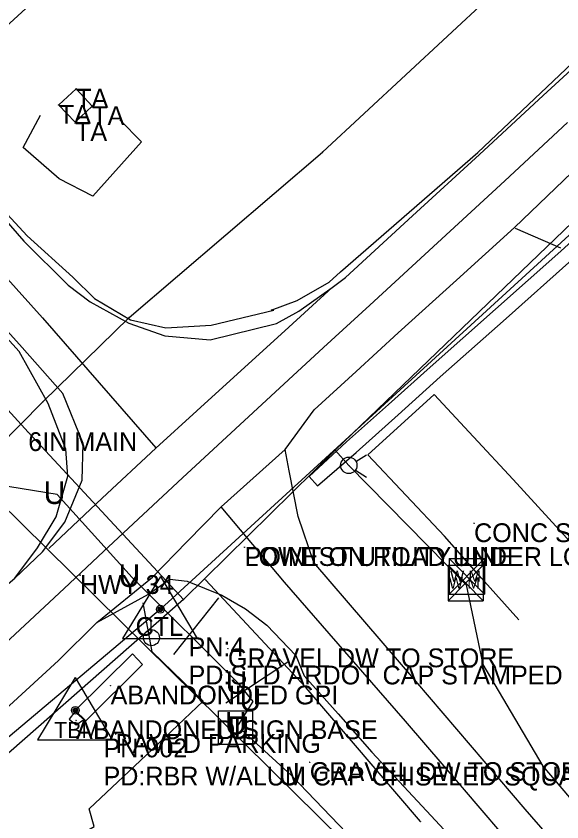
# Model space of a CAD drawing. Extents: x 1660112 to 1662239, y 668919 to 671377.
# Drawn here: x 1661566.2 to 1661711.4, y 669800.5 to 670014.9 of the extents above; entities that cross this region are included whole.
import ezdxf

# ---------------------------------------------------------------- set-up
doc = ezdxf.new("R2010")
doc.units = 0
for name, color, linetype in [('Default', 7, 'Continuous'), ('S_BASELINE', 7, 'Continuous'), ('S_BUILDING', 7, 'Continuous'), ('S_BUILDING_ANNOT', 7, 'Continuous'), ('S_DRIVEWAY', 7, 'Continuous'), ('S_EDGE_CONCRETE', 7, 'Continuous'), ('S_EDGE_PAVEMENT', 7, 'Continuous'), ('S_ELECTRIC_UTILITIES_ANNOT', 7, 'Continuous'), ('S_FIBER_OPTIC_CABLE', 7, 'Continuous'), ('S_MSC_PT_SYM', 7, 'Continuous'), ('S_PAVEMENT_CROWN', 7, 'Continuous'), ('S_PRIMARY_CTL', 7, 'Continuous'), ('S_PRIMARY_CTL_ANNOT', 7, 'Continuous'), ('S_RAILROAD', 7, 'Continuous'), ('S_SANITARY_SEWER', 7, 'Continuous'), ('S_SHOULDER', 7, 'Continuous'), ('S_SIDEWALK', 7, 'Continuous'), ('S_STR_PT_SYM', 7, 'Continuous'), ('S_SURVEY_TEXT_ANNOT', 7, 'Continuous'), ('S_TELEPHONE_UTILITIES', 7, 'Continuous'), ('S_UNDERGROUND_CABLE', 7, 'Continuous'), ('S_UTILITY_POLE', 7, 'Continuous'), ('S_UTL_PT_SYM', 7, 'Continuous'), ('S_WATER_UTILITIES', 7, 'Continuous'), ('S_WATER_UTILITIES_ANNOT', 7, 'Continuous')]:
    doc.layers.add(name, color=color, linetype=linetype)

msp = doc.modelspace()

# ---------------------------------------------------------------- linework, layer by layer
at = {"layer": 'S_BASELINE'}
for p, q in [((1662115.18, 670324.54), (1661604.59, 669857.12)), ((1661604.59, 669857.12), (1660827.54, 669202.71))]:
    msp.add_line(p, q, dxfattribs=at)
at = {"layer": 'S_BUILDING'}
for p, q in [((1661582.19, 669995.6), (1661577.57, 669991.32)), ((1661586.47, 669990.97), (1661582.19, 669995.6)), ((1661577.5, 669991.3), (1661581.89, 669986.74)), ((1661581.89, 669986.74), (1661586.47, 669990.97))]:
    msp.add_line(p, q, dxfattribs=at)
at = {"layer": 'S_DRIVEWAY'}
for points in [[(1661699.03, 669958.54), (1661711.11, 669953.25)], [(1661620.11, 669860.18), (1661608.05, 669845.12)], [(1661638.76, 669843.19), (1661621.98, 669832.17)]]:
    msp.add_lwpolyline(points, dxfattribs=at)
at = {"layer": 'S_EDGE_CONCRETE'}
msp.add_lwpolyline([(1661699.96, 669854.31), (1661690.09, 669865.42), (1661680.21, 669876.53), (1661670, 669887.38), (1661659.78, 669898.24), (1661677.47, 669914.28), (1661687.96, 669902.95), (1661698.44, 669891.62), (1661708.01, 669881.23), (1661717.57, 669870.84)], dxfattribs=at)
for points in [[(1661597.15, 669845.29), (1661581.95, 669830.2), (1661584.79, 669827.42), (1661599.88, 669842.38)], [(1661581.85, 669829.83), (1661580.32, 669827.84), (1661582.15, 669826.33), (1661584.2, 669827.74)]]:
    msp.add_lwpolyline(points, close=True, dxfattribs=at)
at = {"layer": 'S_EDGE_PAVEMENT'}
for points in [[(1661574.88, 669873.32), (1661589.13, 669886.67), (1661603.39, 669900.01), (1661614.27, 669909.9), (1661625.16, 669919.78), (1661637.72, 669931.24), (1661650.28, 669942.7), (1661653.82, 669945.42), (1661671.65, 669961.77), (1661689.49, 669978.13), (1661706.49, 669993.78), (1661723.49, 670009.42), (1661733.12, 670018.24), (1661742.75, 670027.06), (1661756.74, 670039.98), (1661772.34, 670054.33), (1661787.94, 670068.68), (1661803.44, 670083.1), (1661818.95, 670097.53)], [(1661527.23, 669797.8), (1661542.56, 669811.61), (1661560.01, 669827.54), (1661577.47, 669843.46), (1661587.7, 669853.61), (1661602.47, 669865.64), (1661611.61, 669875.02), (1661620.74, 669884.39), (1661637.78, 669899.63), (1661645.56, 669910.14), (1661656.74, 669920.41), (1661667.92, 669930.69), (1661683.38, 669944.69), (1661698.84, 669958.7), (1661714.13, 669973.35), (1661725.28, 669983.31), (1661736.44, 669993.26), (1661746.57, 670002.69), (1661756.7, 670012.13), (1661762.09, 670016.26), (1661771.92, 670025.7), (1661786.96, 670039.58), (1661802.01, 670053.47)], [(1661593.85, 669987.34), (1661599.58, 669981.47), (1661586.66, 669967), (1661577.69, 669971.61), (1661568.05, 669980.02), (1661572.66, 669988.57)], [(1661539.87, 669986.88), (1661549.09, 669976.87), (1661558.69, 669965.95), (1661568.29, 669955.03), (1661580.08, 669943.31), (1661585.93, 669938.89), (1661596.24, 669933.25), (1661605.77, 669929.84), (1661617.85, 669928.83), (1661635.53, 669933.18), (1661641.44, 669936.4), (1661650.28, 669942.7)], [(1661432.01, 669741.93), (1661449.2, 669757.82), (1661461.17, 669768.88), (1661473.15, 669779.94), (1661485.12, 669791), (1661497.09, 669802.06), (1661512.08, 669815.85), (1661527.07, 669829.65), (1661544.05, 669845.51), (1661561.04, 669861.38), (1661565.83, 669865.41), (1661573.24, 669872.37), (1661579.19, 669880.3), (1661583.76, 669891.47), (1661584.04, 669901.2), (1661578.64, 669914.49), (1661567.83, 669926.75), (1661553.64, 669942.48), (1661544.41, 669952.61), (1661535.19, 669962.75), (1661525.02, 669973.56)], [(1661814.09, 669678.75), (1661801.76, 669692.17), (1661789.43, 669705.59), (1661777.09, 669719), (1661764.76, 669732.42), (1661756.13, 669742.08), (1661747.5, 669751.75), (1661738.87, 669761.41), (1661730.24, 669771.08), (1661715.94, 669787.51), (1661701.63, 669803.94), (1661687.11, 669820.98), (1661672.59, 669838.02), (1661659.03, 669853.81), (1661645.46, 669869.6), (1661641.26, 669881.81), (1661638.86, 669893.94), (1661637.77, 669899.62)], [(1661587.69, 669853.6), (1661601.46, 669861.14), (1661607.16, 669865.14), (1661611.7, 669864.55), (1661620.99, 669860.83), (1661627.24, 669857.2), (1661632.97, 669852.86), (1661640.64, 669844.85), (1661642.88, 669839.37), (1661651.88, 669829.25), (1661660.88, 669819.13), (1661676.63, 669802.18), (1661692.38, 669785.23), (1661706.18, 669769.2), (1661719.98, 669753.17), (1661729.11, 669743.19), (1661738.25, 669733.2), (1661747.38, 669723.22), (1661756.51, 669713.23), (1661766.96, 669701.85), (1661777.42, 669690.46), (1661787.87, 669679.07), (1661798.32, 669667.68)], [(1661516.06, 669787.26), (1661526.46, 669785.99), (1661541.4, 669768), (1661544.7, 669763.68), (1661549.49, 669767.62), (1661547.73, 669791.69), (1661563.07, 669792.95), (1661578.42, 669794.22), (1661586.99, 669799.3), (1661585.63, 669803.97), (1661600.8, 669818.33), (1661615.97, 669832.69), (1661602.41, 669845.81), (1661600.05, 669858.83)]]:
    msp.add_lwpolyline(points, dxfattribs=at)
at = {"layer": 'S_FIBER_OPTIC_CABLE'}
for p, q in [((1661647.72, 669978.74), (1661720.75, 670046.56)), ((1661596.3, 669934.77), (1661647.72, 669978.74)), ((1661573.33, 669912.35), (1661596.3, 669934.77)), ((1661539.32, 669878.16), (1661573.33, 669912.35))]:
    msp.add_line(p, q, dxfattribs=at)
at = {"layer": 'S_MSC_PT_SYM'}
for points in [[(1661688.07, 669879.98), (1661688.07, 669880.03), (1661688.07, 669879.98), (1661688.02, 669879.98), (1661688.07, 669879.98), (1661688.07, 669879.93), (1661688.07, 669879.98), (1661688.12, 669879.98)], [(1661627.02, 669873.64), (1661627.02, 669873.69), (1661627.02, 669873.64), (1661626.97, 669873.64), (1661627.02, 669873.64), (1661627.02, 669873.59), (1661627.02, 669873.64), (1661627.07, 669873.64)], [(1661583.22, 669866.19), (1661583.22, 669866.24), (1661583.22, 669866.19), (1661583.17, 669866.19), (1661583.22, 669866.19), (1661583.22, 669866.14), (1661583.22, 669866.19), (1661583.27, 669866.19)], [(1661622.59, 669846.68), (1661622.59, 669846.73), (1661622.59, 669846.68), (1661622.54, 669846.68), (1661622.59, 669846.68), (1661622.59, 669846.63), (1661622.59, 669846.68), (1661622.64, 669846.68)], [(1661591.37, 669836.8), (1661591.37, 669836.85), (1661591.37, 669836.8), (1661591.32, 669836.8), (1661591.37, 669836.8), (1661591.37, 669836.75), (1661591.37, 669836.8), (1661591.42, 669836.8)], [(1661582.16, 669827.55), (1661582.16, 669827.6), (1661582.16, 669827.55), (1661582.11, 669827.55), (1661582.16, 669827.55), (1661582.16, 669827.5), (1661582.16, 669827.55), (1661582.21, 669827.55)], [(1661592.72, 669823.9), (1661592.72, 669823.95), (1661592.72, 669823.9), (1661592.67, 669823.9), (1661592.72, 669823.9), (1661592.72, 669823.85), (1661592.72, 669823.9), (1661592.77, 669823.9)], [(1661644.36, 669816.42), (1661644.36, 669816.47), (1661644.36, 669816.42), (1661644.31, 669816.42), (1661644.36, 669816.42), (1661644.36, 669816.37), (1661644.36, 669816.42), (1661644.41, 669816.42)]]:
    msp.add_lwpolyline(points, dxfattribs=at)
at = {"layer": 'S_PAVEMENT_CROWN'}
for points in [[(1661503.87, 669793.54), (1661518.86, 669807.19), (1661533.86, 669820.84), (1661551.21, 669836.85), (1661568.55, 669852.86), (1661579.03, 669862.68), (1661589.51, 669872.49), (1661600, 669882.3), (1661610.48, 669892.12), (1661619.87, 669900.79), (1661629.26, 669909.46), (1661638.66, 669918.13), (1661648.05, 669926.8), (1661660.37, 669938.02), (1661678.3, 669954.58), (1661696.23, 669971.14), (1661712.97, 669986.61)], [(1661532.25, 669980.05), (1661542.23, 669969.08), (1661553.09, 669957.19), (1661563.16, 669945.92), (1661573.22, 669934.64), (1661588.29, 669917.36), (1661603.37, 669900.08)], [(1661620.71, 669884.35), (1661629.13, 669874.34), (1661637.54, 669864.33), (1661653.63, 669845.85), (1661669.73, 669827.36), (1661684.9, 669809.66), (1661700.07, 669791.96), (1661714.09, 669775.77), (1661728.11, 669759.57), (1661736.98, 669749.7), (1661745.86, 669739.83), (1661754.73, 669729.96), (1661763.61, 669720.09), (1661774.08, 669708.76), (1661784.55, 669697.43), (1661795.03, 669686.1), (1661805.5, 669674.77)]]:
    msp.add_lwpolyline(points, dxfattribs=at)
at = {"layer": 'S_PRIMARY_CTL'}
for p, q in [((1661604.59, 669865.82), (1661594.55, 669849.3)), ((1661604.59, 669865.82), (1661614.41, 669849.3)), ((1661594.55, 669849.3), (1661614.41, 669849.3)), ((1661581.97, 669838.92), (1661571.93, 669822.4)), ((1661581.97, 669838.92), (1661591.79, 669822.4)), ((1661571.93, 669822.4), (1661591.79, 669822.4))]:
    msp.add_line(p, q, dxfattribs=at)
for centre, radius in [((1661604.59, 669857.12), 1.04), ((1661604.59, 669857.12), 0.609), ((1661604.59, 669857.12), 0.344), ((1661581.97, 669830.22), 1.04), ((1661581.97, 669830.22), 0.609), ((1661581.97, 669830.22), 0.344)]:
    msp.add_circle(centre, radius, dxfattribs=at)
at = {"layer": 'S_RAILROAD'}
msp.add_line((1661541.88, 669992.49), (1661596.12, 670041.9), dxfattribs=at)
at = {"layer": 'S_SANITARY_SEWER'}
msp.add_line((1661704.02, 669745.54), (1661292.91, 670150.69), dxfattribs=at)
at = {"layer": 'S_SHOULDER'}
for points in [[(1661544.18, 669990.78), (1661545.38, 669989.16), (1661549.73, 669977.29), (1661559.45, 669966.88), (1661569.17, 669956.48), (1661581.29, 669945.51), (1661587.1, 669939.82), (1661596.61, 669934.16), (1661606.09, 669931.97), (1661618.1, 669932.69), (1661634.83, 669936.71), (1661634.11, 669936.74), (1661641.01, 669939.29), (1661649.51, 669944.11), (1661652.54, 669946.88), (1661670.8, 669962.78), (1661689.06, 669978.67), (1661705.8, 669994.5), (1661722.55, 670010.32)], [(1661565.9, 669865.41), (1661571.88, 669873.46), (1661576.91, 669881.7), (1661580, 669892.53), (1661579.44, 669899.68), (1661574.75, 669911.86), (1661567.03, 669925.66), (1661552.68, 669941.47), (1661543.51, 669951.68), (1661534.34, 669961.89), (1661525.37, 669969.85), (1661523.19, 669968.6), (1661521.62, 669970.1)]]:
    msp.add_lwpolyline(points, dxfattribs=at)
at = {"layer": 'S_SIDEWALK'}
for points in [[(1661646.43, 669889.94), (1661644.23, 669892.47), (1661654.17, 669901.69), (1661665.3, 669911.6), (1661676.42, 669921.52), (1661693.78, 669936.97), (1661711.13, 669952.42), (1661719.33, 669959.85), (1661733.17, 669972.43), (1661747.01, 669985), (1661757.67, 669994.65), (1661768.33, 670004.3), (1661781.51, 670016.3), (1661797.89, 670031.01), (1661814.27, 670045.72), (1661827.95, 670058.03), (1661841.63, 670070.34)], [(1661646.44, 669889.96), (1661656.73, 669898.86), (1661667.89, 669908.89), (1661679.06, 669918.92), (1661696.59, 669934.52), (1661714.11, 669950.11), (1661722.27, 669957.66), (1661735.99, 669969.95), (1661749.7, 669982.24), (1661760.22, 669991.84), (1661770.74, 670001.44), (1661784.06, 670013.42), (1661800.45, 670028.21), (1661816.83, 670043.01), (1661830.55, 670055.24), (1661844.26, 670067.47)]]:
    msp.add_lwpolyline(points, dxfattribs=at)
at = {"layer": 'S_STR_PT_SYM'}
for points in [[(1661582.19, 669995.6), (1661582.19, 669995.65), (1661582.19, 669995.6), (1661582.14, 669995.6), (1661582.19, 669995.6), (1661582.19, 669995.55), (1661582.19, 669995.6), (1661582.24, 669995.6)], [(1661577.5, 669991.3), (1661577.5, 669991.35), (1661577.5, 669991.3), (1661577.45, 669991.3), (1661577.5, 669991.3), (1661577.5, 669991.25), (1661577.5, 669991.3), (1661577.55, 669991.3)], [(1661577.57, 669991.32), (1661577.57, 669991.37), (1661577.57, 669991.32), (1661577.52, 669991.32), (1661577.57, 669991.32), (1661577.57, 669991.27), (1661577.57, 669991.32), (1661577.62, 669991.32)], [(1661586.47, 669990.97), (1661586.47, 669991.02), (1661586.47, 669990.97), (1661586.42, 669990.97), (1661586.47, 669990.97), (1661586.47, 669990.92), (1661586.47, 669990.97), (1661586.52, 669990.97)], [(1661581.89, 669986.74), (1661581.89, 669986.79), (1661581.89, 669986.74), (1661581.84, 669986.74), (1661581.89, 669986.74), (1661581.89, 669986.69), (1661581.89, 669986.74), (1661581.94, 669986.74)]]:
    msp.add_lwpolyline(points, dxfattribs=at)
at = {"layer": 'S_TELEPHONE_UTILITIES'}
msp.add_lwpolyline([(1661620.09, 669821.1), (1661620.09, 669830.1), (1661629.09, 669830.1), (1661629.09, 669821.1)], close=True, dxfattribs=at)
at = {"layer": 'S_UNDERGROUND_CABLE'}
for p, q in [((1661577.17, 669887.67), (1661559.59, 669890.51)), ((1661597.09, 669865.59), (1661577.17, 669887.67)), ((1661625.58, 669837.15), (1661597.09, 669865.59)), ((1661629.29, 669832.59), (1661625.58, 669837.15)), ((1661625.43, 669826.33), (1661629.29, 669832.59)), ((1661639.6, 669812.78), (1661626.1, 669825.11)), ((1661660.31, 669791.28), (1661639.6, 669812.78))]:
    msp.add_line(p, q, dxfattribs=at)
at = {"layer": 'S_UTILITY_POLE'}
msp.add_line((1661602.11, 669851.69), (1661602.11, 669853.8), dxfattribs=at)
msp.add_circle((1661602.23, 669849.55), 2.13, dxfattribs=at)
at = {"layer": 'S_UTL_PT_SYM'}
for points in [[(1661647.72, 669978.74), (1661647.72, 669978.79), (1661647.72, 669978.74), (1661647.67, 669978.74), (1661647.72, 669978.74), (1661647.72, 669978.69), (1661647.72, 669978.74), (1661647.77, 669978.74)], [(1661596.3, 669934.77), (1661596.3, 669934.82), (1661596.3, 669934.77), (1661596.25, 669934.77), (1661596.3, 669934.77), (1661596.3, 669934.72), (1661596.3, 669934.77), (1661596.35, 669934.77)], [(1661573.33, 669912.35), (1661573.33, 669912.4), (1661573.33, 669912.35), (1661573.28, 669912.35), (1661573.33, 669912.35), (1661573.33, 669912.3), (1661573.33, 669912.35), (1661573.38, 669912.35)], [(1661569.45, 669904.22), (1661569.45, 669904.27), (1661569.45, 669904.22), (1661569.4, 669904.22), (1661569.45, 669904.22), (1661569.45, 669904.17), (1661569.45, 669904.22), (1661569.5, 669904.22)], [(1661651.15, 669899.47), (1661651.15, 669899.52), (1661651.15, 669899.47), (1661651.1, 669899.47), (1661651.15, 669899.47), (1661651.15, 669899.42), (1661651.15, 669899.47), (1661651.2, 669899.47)], [(1661651.15, 669899.47), (1661651.15, 669899.52), (1661651.15, 669899.47), (1661651.1, 669899.47), (1661651.15, 669899.47), (1661651.15, 669899.42), (1661651.15, 669899.47), (1661651.2, 669899.47)], [(1661654.76, 669895.41), (1661654.76, 669895.46), (1661654.76, 669895.41), (1661654.71, 669895.41), (1661654.76, 669895.41), (1661654.76, 669895.36), (1661654.76, 669895.41), (1661654.81, 669895.41)], [(1661627.02, 669873.64), (1661627.02, 669873.69), (1661627.02, 669873.64), (1661626.97, 669873.64), (1661627.02, 669873.64), (1661627.02, 669873.59), (1661627.02, 669873.64), (1661627.07, 669873.64)], [(1661616.63, 669864.98), (1661616.63, 669865.03), (1661616.63, 669864.98), (1661616.58, 669864.98), (1661616.63, 669864.98), (1661616.63, 669864.93), (1661616.63, 669864.98), (1661616.68, 669864.98)], [(1661685.96, 669863.63), (1661685.96, 669863.68), (1661685.96, 669863.63), (1661685.91, 669863.63), (1661685.96, 669863.63), (1661685.96, 669863.58), (1661685.96, 669863.63), (1661686.01, 669863.63)], [(1661610.79, 669859.67), (1661610.79, 669859.72), (1661610.79, 669859.67), (1661610.74, 669859.67), (1661610.79, 669859.67), (1661610.79, 669859.62), (1661610.79, 669859.67), (1661610.84, 669859.67)], [(1661610.79, 669859.67), (1661610.79, 669859.72), (1661610.79, 669859.67), (1661610.74, 669859.67), (1661610.79, 669859.67), (1661610.79, 669859.62), (1661610.79, 669859.67), (1661610.84, 669859.67)], [(1661690.42, 669842.42), (1661690.42, 669842.47), (1661690.42, 669842.42), (1661690.37, 669842.42), (1661690.42, 669842.42), (1661690.42, 669842.37), (1661690.42, 669842.42), (1661690.47, 669842.42)], [(1661643.43, 669836.2), (1661643.43, 669836.25), (1661643.43, 669836.2), (1661643.38, 669836.2), (1661643.43, 669836.2), (1661643.43, 669836.15), (1661643.43, 669836.2), (1661643.48, 669836.2)], [(1661706.34, 669815.34), (1661706.34, 669815.39), (1661706.34, 669815.34), (1661706.29, 669815.34), (1661706.34, 669815.34), (1661706.34, 669815.29), (1661706.34, 669815.34), (1661706.39, 669815.34)], [(1661673.85, 669800.67), (1661673.85, 669800.72), (1661673.85, 669800.67), (1661673.8, 669800.67), (1661673.85, 669800.67), (1661673.85, 669800.62), (1661673.85, 669800.67), (1661673.9, 669800.67)]]:
    msp.add_lwpolyline(points, dxfattribs=at)
at = {"layer": 'S_WATER_UTILITIES'}
for p, q in [((1661722.37, 669967.91), (1661651.15, 669899.47)), ((1661569.45, 669904.22), (1661528.82, 669948.66)), ((1661610.79, 669859.67), (1661569.45, 669904.22)), ((1661651.15, 669899.47), (1661610.79, 669859.67)), ((1661651.15, 669899.47), (1661654.76, 669895.41)), ((1661656.64, 669896.46), (1661659.47, 669898.19)), ((1661654.76, 669895.41), (1661685.96, 669863.63)), ((1661656.52, 669894.15), (1661659.43, 669892.23)), ((1661681.49, 669870.65), (1661690.83, 669870.65)), ((1661681.49, 669870.65), (1661681.49, 669861.16)), ((1661681.49, 669870.65), (1661690.83, 669861.16)), ((1661690.83, 669870.65), (1661681.49, 669861.16)), ((1661690.83, 669870.65), (1661690.83, 669861.16)), ((1661681.17, 669868.84), (1661690.51, 669868.84)), ((1661681.17, 669868.84), (1661681.17, 669859.35)), ((1661681.17, 669868.84), (1661690.51, 669859.35)), ((1661690.51, 669868.84), (1661681.17, 669859.35)), ((1661690.51, 669868.84), (1661690.51, 669859.35)), ((1661643.43, 669836.2), (1661616.63, 669864.98)), ((1661685.96, 669863.63), (1661690.42, 669842.42)), ((1661610.79, 669859.67), (1661522.71, 669782.51)), ((1661681.49, 669861.16), (1661690.83, 669861.16)), ((1661681.17, 669859.35), (1661690.51, 669859.35)), ((1661690.42, 669842.42), (1661706.34, 669815.34)), ((1661673.85, 669800.67), (1661643.43, 669836.2)), ((1661706.34, 669815.34), (1661738.35, 669777.77))]:
    msp.add_line(p, q, dxfattribs=at)
msp.add_circle((1661654.74, 669895.41), 2.18, dxfattribs=at)

# ---------------------------------------------------------------- texts
at = {"layer": 'Default'}
for p in [(1661573.54, 669885.12), (1661593.46, 669863.05), (1661621.96, 669834.61), (1661625.67, 669830.05), (1661621.8, 669823.79), (1661622.47, 669822.57), (1661635.97, 669810.24)]:
    msp.add_text('U', height=6, rotation=360, dxfattribs=at).set_placement(p)
at = {"layer": 'S_BUILDING_ANNOT'}
for p in [(1661582.19, 669990.6), (1661577.57, 669986.32), (1661586.47, 669985.97), (1661581.89, 669981.74)]:
    msp.add_text('TA', height=5, dxfattribs=at).set_placement(p)
at = {"layer": 'S_ELECTRIC_UTILITIES_ANNOT'}
msp.add_text('LOWEST UTILITY LINE', height=5, dxfattribs=at).set_placement((1661627.02, 669868.64))
at = {"layer": 'S_PRIMARY_CTL'}
for s, height, p in [('CTL', 5, (1661598, 669850.04)), ('TBM', 4.287, (1661576.31, 669822.83))]:
    msp.add_text(s, height=height, rotation=360, dxfattribs=at).set_placement(p)
at = {"layer": 'S_PRIMARY_CTL_ANNOT'}
for s, p in [('PN:4', (1661612.09, 669844.62)), ('PD:STD ARDOT CAP STAMPED PN:4', (1661612.09, 669837.12)), ('PN:902', (1661589.47, 669817.72)), ('PD:RBR W/ALUM CAP CHISELED SQUARE ', (1661589.47, 669810.22))]:
    msp.add_text(s, height=5, dxfattribs=at).set_placement(p)
at = {"layer": 'S_SURVEY_TEXT_ANNOT'}
for s, p in [('CONC SLAB', (1661688.07, 669874.98)), ('POINT ON ROAD UNDER LOWES', (1661627.02, 669868.64)), ('HWY 34', (1661583.22, 669861.19)), ('GRAVEL DW TO STORE', (1661622.59, 669841.68)), ('ABANDONDED GPI', (1661591.37, 669831.8)), ('ABANDONED SIGN BASE', (1661582.16, 669822.55)), ('PAVED PARKING', (1661592.72, 669818.9)), ('GRAVEL DW TO STORE', (1661644.36, 669811.42))]:
    msp.add_text(s, height=5, dxfattribs=at).set_placement(p)
at = {"layer": 'S_TELEPHONE_UTILITIES'}
msp.add_text('T', height=6, rotation=360, dxfattribs=at).set_placement((1661622.65, 669822.6))
at = {"layer": 'S_WATER_UTILITIES'}
for p in [(1661681.69, 669864.42), (1661681.37, 669862.61)]:
    msp.add_text('W M', height=3, rotation=360, dxfattribs=at).set_placement(p)
at = {"layer": 'S_WATER_UTILITIES_ANNOT'}
msp.add_text('6IN MAIN', height=5, dxfattribs=at).set_placement((1661569.45, 669899.22))

doc.saveas('drawing.dxf')
